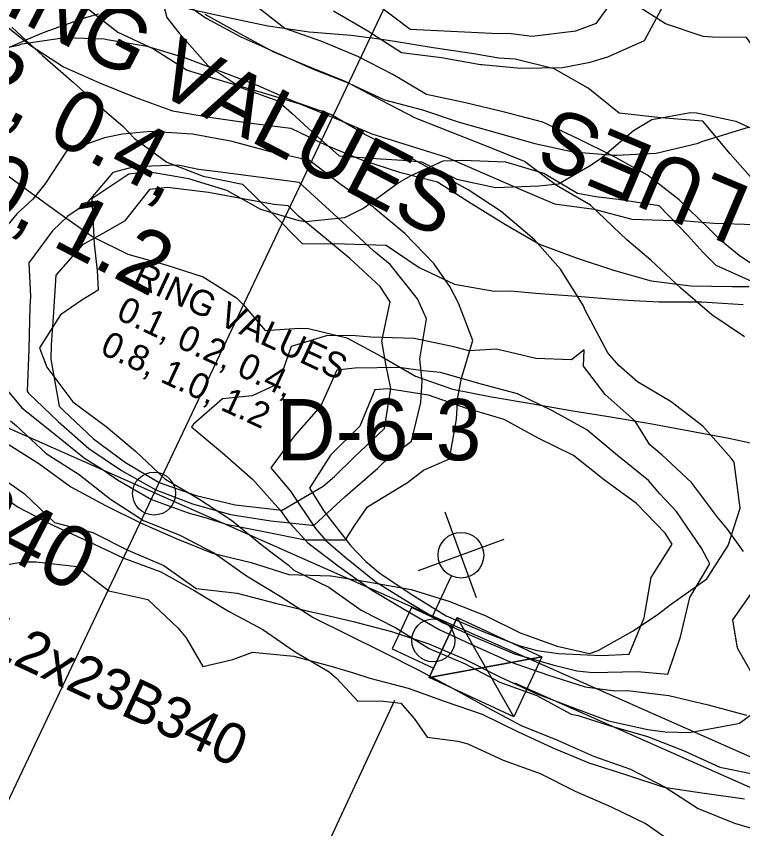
# Model space of a CAD drawing. Extents: x 1638506 to 1658005, y 834807 to 846788.
# Drawn here: x 1639685 to 1639827.3, y 842760 to 842919.2 of the extents above; entities that cross this region are included whole.
import ezdxf

# ---------------------------------------------------------------- set-up
doc = ezdxf.new("R2010")
doc.units = 0
for name, color, linetype in [('Default', 7, 'Continuous'), ('Old_Level_1', 7, 'Continuous'), ('Old_Level_2', 7, 'Continuous'), ('Scratch_Level_0', 7, 'Continuous')]:
    doc.layers.add(name, color=color, linetype=linetype)

msp = doc.modelspace()

# ---------------------------------------------------------------- linework, layer by layer
at = {"layer": 'Default'}
for p, q in [((1639775.15, 842805.23), (1639769.04, 842822.02)), ((1639780.52, 842816.67), (1639763.7, 842810.57)), ((1639772.12, 842813.64), (1639772.12, 842813.64)), ((1639766.45, 842801.47), (1639770.23, 842809.58)), ((1639773.64, 842809.38), (1639773.64, 842809.38)), ((1639782.45, 842781.94), (1639771.36, 842801.42)), ((1639787.93, 842793.69), (1639765.88, 842789.67)), ((1639782.61, 842788.6), (1640040.31, 842674.21)), ((1639689.98, 842636.62), (1639759.17, 842785.21))]:
    msp.add_line(p, q, dxfattribs=at)
for points in [[(1639766.73, 842791.5), (1639770.5, 842799.58), (1639762.39, 842803.36), (1639758.62, 842795.28)], [(1639782.45, 842781.94), (1639765.88, 842789.67), (1639771.36, 842801.42), (1639787.93, 842793.69)], [(1639776.9, 842791.68), (1639771.36, 842801.42), (1639765.88, 842789.67)], [(1639776.9, 842791.68), (1639787.93, 842793.69), (1639782.45, 842781.94)]]:
    msp.add_lwpolyline(points, close=True, dxfattribs=at)
msp.add_circle((1639772.1, 842813.61), 4.47, dxfattribs=at)
at = {"layer": 'Old_Level_1'}
for points in [[(1639755.76, 842921.47), (1639762.13, 842916.6), (1639770.13, 842916.23), (1639778.14, 842915.86), (1639781.95, 842915.75), (1639786.07, 842915.28), (1639794.59, 842916.33), (1639798.63, 842917.82), (1639803.27, 842924.27)], [(1639715.75, 842923.38), (1639722.21, 842918.76), (1639729.03, 842915.14), (1639736.03, 842912.01), (1639743.02, 842908.85), (1639750.16, 842906.08), (1639757.1, 842902.78), (1639764.54, 842900.85), (1639771.78, 842898.38), (1639779.17, 842896.31), (1639786.54, 842894.21), (1639794.1, 842892.6), (1639802.01, 842891.98), (1639802.61, 842891.95), (1639810.29, 842892.36), (1639818.57, 842894.28), (1639819.25, 842894.62), (1639828.42, 842897.43)], [(1639698.61, 842921.03), (1639704.93, 842916.03), (1639711.89, 842912.78), (1639718.52, 842908.61), (1639725.83, 842906.35), (1639733.2, 842904.22), (1639740.54, 842902.02), (1639747.62, 842899.1), (1639754.67, 842896.11), (1639761.99, 842893.87), (1639769.29, 842891.55), (1639776.33, 842888.52), (1639783.34, 842885.42), (1639790.4, 842882.45), (1639798.15, 842881.38), (1639805.57, 842879.4), (1639813.63, 842879.17), (1639815.45, 842879.13), (1639821.58, 842878.64), (1639829.62, 842878.35)], [(1639833.02, 842867.94), (1639826.6, 842872.28), (1639823, 842875.22), (1639820.63, 842877.58), (1639814.8, 842883.18), (1639808.61, 842888.01), (1639801.91, 842891.73), (1639795.07, 842895.17), (1639788.14, 842898.4), (1639780.62, 842900.38), (1639773.01, 842902.17), (1639765.35, 842903.85), (1639758.74, 842907.77), (1639751.93, 842911.27), (1639744.87, 842914.24), (1639737.62, 842916.78), (1639731.41, 842921.57)], [(1639747.15, 842920.19), (1639753.88, 842916.31), (1639760.48, 842912.08), (1639768.26, 842911.07), (1639775.91, 842909.73), (1639776.25, 842909.68), (1639783.78, 842908.98), (1639791.98, 842909.14), (1639797.38, 842910.13), (1639800.87, 842911.21), (1639808.02, 842914.4), (1639811.68, 842921.21)], [(1639827.63, 842856.39), (1639821.19, 842860.68), (1639815.18, 842865.89), (1639809.29, 842871.37), (1639804.61, 842875.36), (1639803.3, 842876.62), (1639797.44, 842882.15), (1639790.79, 842885.99), (1639784.56, 842890.72), (1639777.46, 842893.61), (1639770.31, 842896.38), (1639763.19, 842899.21), (1639756.39, 842902.73), (1639749.63, 842906.32), (1639742.53, 842909.2), (1639735.46, 842912.14), (1639728.71, 842915.78), (1639722, 842919.48)], [(1639681.43, 842918.55), (1639687.73, 842913.49), (1639694.31, 842909.22), (1639701.32, 842906.1), (1639708.43, 842903.26), (1639715.62, 842900.65), (1639723.28, 842899.34), (1639731.01, 842898.21), (1639738.79, 842897.21), (1639745.72, 842893.88), (1639752.8, 842890.99), (1639760.09, 842888.65), (1639767.54, 842886.74), (1639774.14, 842882.51), (1639780.79, 842878.4), (1639787.5, 842874.49), (1639794.69, 842871.87), (1639801.96, 842869.46), (1639809.33, 842867.36), (1639817.12, 842866.39), (1639825.2, 842866.23), (1639828.55, 842866.22)], [(1639825.57, 842831.82), (1639824.98, 842832.61), (1639819.46, 842838.86), (1639813.26, 842843.66), (1639806.64, 842847.57), (1639803.03, 842850.77), (1639800.84, 842853.25), (1639796.35, 842861.71), (1639796.11, 842862.44), (1639791.61, 842869.65), (1639786.47, 842875.37), (1639786.02, 842875.77), (1639779.99, 842880.93), (1639773.51, 842885.13), (1639766.81, 842888.86), (1639760.12, 842892.62), (1639753.25, 842896), (1639746.63, 842899.9), (1639739.39, 842902.47), (1639732.39, 842905.55), (1639725.21, 842908.26), (1639718.04, 842911), (1639710.66, 842913.26), (1639702.82, 842914.56), (1639702.23, 842914.65), (1639694.54, 842914.91), (1639686.13, 842913.72), (1639685.42, 842913.44), (1639676.05, 842911.44)], [(1639771.25, 842840.26), (1639771.47, 842844.57), (1639772.19, 842848.27), (1639774.42, 842855.67), (1639771.62, 842862.99), (1639769.91, 842866.21), (1639766.79, 842870.74), (1639761.11, 842876.64), (1639755.29, 842881.47), (1639755.02, 842881.68), (1639748.65, 842886.14), (1639742.44, 842890.92), (1639734.79, 842892.6), (1639727.28, 842894.61), (1639726.95, 842894.69), (1639719.51, 842896.04), (1639711.33, 842896.6), (1639705.86, 842896.08), (1639702.29, 842895.32), (1639694.89, 842892.75), (1639690.65, 842886.29), (1639688.27, 842883.36), (1639685.12, 842880.43), (1639680.06, 842874.35)], [(1639764.25, 842843.53), (1639764.49, 842847.69), (1639764.08, 842852.05), (1639765.36, 842859.89), (1639763.56, 842863.8), (1639758.27, 842870.57), (1639755.03, 842873.15), (1639752.26, 842875.76), (1639746.33, 842881.16), (1639740.41, 842886.57), (1639732.47, 842887.63), (1639724.52, 842888.7), (1639720.74, 842889.14), (1639716.68, 842889.96), (1639708.09, 842889.66), (1639703.94, 842888.53), (1639698.76, 842882.51), (1639695.16, 842880.02), (1639692.12, 842877.16), (1639687.49, 842870.88), (1639687.81, 842864.27), (1639687.69, 842862.35), (1639687.52, 842853.99), (1639687.15, 842845.72), (1639687.44, 842845.37), (1639693.27, 842839.77), (1639699.26, 842834.51), (1639705.67, 842830.17), (1639712.35, 842826.39), (1639719.54, 842823.7), (1639726.99, 842821.57), (1639734.87, 842820.37), (1639742.91, 842819.51), (1639743.36, 842819.51), (1639749.46, 842825.11), (1639755.75, 842830.61), (1639757.15, 842831.94), (1639762.42, 842835.94), (1639764.25, 842843.53)], [(1639758.36, 842846.28), (1639757.46, 842850.72), (1639756.64, 842855.52), (1639758.21, 842863.23), (1639756.26, 842866.25), (1639750.37, 842871.71), (1639744.28, 842876.75), (1639740.27, 842880.03), (1639738.29, 842882.01), (1639735.5, 842882.26), (1639730.41, 842883.22), (1639722.64, 842884.65), (1639714.66, 842885.65), (1639711.1, 842885.2), (1639706.2, 842879.04), (1639702, 842876.59), (1639698.01, 842874.42), (1639692.75, 842868.43), (1639692.29, 842860.21), (1639691.88, 842854.9), (1639691.83, 842851.98), (1639693.44, 842842.78), (1639694.29, 842841.96), (1639700.14, 842836.4), (1639706.42, 842831.77), (1639713.02, 842827.83), (1639720.28, 842825.3), (1639727.87, 842823.47), (1639735.89, 842822.56), (1639737.07, 842822.44), (1639745.15, 842827.11), (1639747.35, 842829.03), (1639751.15, 842832.75), (1639757.16, 842838.39), (1639758.36, 842846.28)], [(1639680.99, 842848.59), (1639686.1, 842842.5), (1639692.25, 842837.58), (1639698.37, 842832.61), (1639701.83, 842830.43), (1639704.84, 842828.37), (1639711.48, 842824.53), (1639718.7, 842821.91), (1639722.21, 842820.93), (1639726.1, 842819.68), (1639733.85, 842818.18), (1639741.57, 842816.63), (1639749.52, 842816.64), (1639751.34, 842819.48), (1639753.83, 842823.06), (1639761.63, 842827.87), (1639764.79, 842830.23), (1639769.84, 842832.48), (1639771.25, 842840.26)], [(1639682.93, 842835.69), (1639689.44, 842831.55), (1639695.74, 842826.98), (1639702.5, 842823.37), (1639709.37, 842819.98), (1639716.37, 842816.9), (1639723.48, 842814.04), (1639731.04, 842812.15), (1639738.39, 842809.82), (1639746.57, 842809.57), (1639746.71, 842809.55), (1639754.56, 842808.29), (1639762.36, 842806.91), (1639769.73, 842804.63), (1639776.85, 842801.79), (1639783.72, 842798.43), (1639790.92, 842795.77), (1639797.24, 842794.38), (1639798.99, 842794.97), (1639805.81, 842798.83), (1639810.76, 842802.1), (1639813.09, 842803.87), (1639820.21, 842808.99), (1639824.41, 842815.48), (1639826.8, 842822.8), (1639825.57, 842831.82)], [(1639680.3, 842830.06), (1639686.66, 842825.6), (1639692.51, 842820.04), (1639700.04, 842818.08), (1639706.85, 842814.58), (1639713.9, 842811.61), (1639720.24, 842807.11), (1639728.26, 842806.2), (1639735.77, 842804.2), (1639743.35, 842802.36), (1639744.1, 842802.28), (1639750.98, 842800.63), (1639758.52, 842798.68), (1639765.82, 842796.24), (1639772.88, 842793.28), (1639779.69, 842789.78), (1639786.63, 842786.56), (1639793.8, 842783.83), (1639801, 842781.18), (1639808.66, 842779.5), (1639812.1, 842779.01), (1639816.83, 842778.92), (1639826.03, 842780.56), (1639826.61, 842780.69), (1639833.65, 842785.85)], [(1639679.95, 842811.21), (1639686.35, 842812.33), (1639688.9, 842812.31), (1639696.93, 842811.42), (1639703.15, 842806.66), (1639710.8, 842804.96), (1639716.64, 842799.38), (1639718.29, 842797.43), (1639721.55, 842791.81), (1639727.44, 842793.17), (1639731.31, 842794.64), (1639739.37, 842793.82), (1639746.89, 842791.84), (1639751.25, 842790.5), (1639754.25, 842789.54), (1639761.78, 842787.58), (1639768.99, 842784.94), (1639776.28, 842782.46), (1639783.15, 842779.09), (1639790.1, 842775.9), (1639797.17, 842772.97), (1639804.5, 842770.57), (1639811.84, 842768.21), (1639819.71, 842767), (1639819.77, 842766.99), (1639827.63, 842765.88)]]:
    msp.add_lwpolyline(points, dxfattribs=at)
msp.add_circle((1639712.02, 842825.68), 4.21, dxfattribs=at)
at = {"layer": 'Old_Level_2'}
for p, q in [((1639805.78, 843023.38), (1639662.97, 842722.48)), ((1639680.46, 842839.86), (1639907.01, 842739.41))]:
    msp.add_line(p, q, dxfattribs=at)
at = {"layer": 'Scratch_Level_0'}
for points in [[(1639712.78, 842925.67), (1639714.52, 842918.88), (1639716.92, 842915.84), (1639722.53, 842909.48), (1639729.02, 842905.18), (1639736.22, 842902.57), (1639739.01, 842900.18), (1639742.24, 842897.17), (1639748.27, 842891.8), (1639756.33, 842891.2), (1639760.73, 842890.97), (1639764.39, 842890.62), (1639771.27, 842887.26), (1639778.88, 842885.59), (1639787.35, 842885.97), (1639791.2, 842886.36), (1639797.29, 842889.83), (1639799.34, 842891.22), (1639805.88, 842896.75), (1639809.46, 842898.93), (1639817.04, 842900.33), (1639818.31, 842900.21), (1639825.94, 842898.61), (1639832.9, 842895.42)], [(1639908.21, 842853.63), (1639902.07, 842858.41), (1639896.06, 842863.44), (1639890.06, 842868.47), (1639884.12, 842873.64), (1639883.49, 842874.18), (1639878.21, 842878.87), (1639872.24, 842883.96), (1639866.28, 842889.09), (1639860.23, 842894.04), (1639853.68, 842898.01), (1639846.42, 842900.65), (1639839.32, 842903.56), (1639833.09, 842908.17), (1639831.92, 842909.58), (1639828, 842914.97), (1639821.34, 842915.08), (1639819.51, 842915.22), (1639812.16, 842917.67), (1639805.69, 842921.8)], [(1639701.09, 842919.58), (1639698.12, 842918.74), (1639690.64, 842916.06), (1639688.44, 842915.15), (1639679.52, 842911.24)], [(1639830.23, 842886.06), (1639824.82, 842892.24), (1639819.49, 842898.58), (1639811.24, 842899.29), (1639803.07, 842900.16), (1639797, 842905.06), (1639790.34, 842908.84), (1639782.72, 842910.77), (1639779.49, 842910.96), (1639774.64, 842911.81), (1639766.64, 842913), (1639758.69, 842914.3), (1639755.64, 842914.72), (1639750.63, 842915.38), (1639742.36, 842916.04), (1639734.33, 842917.18), (1639734.3, 842917.19), (1639726.57, 842918.85), (1639718.83, 842920.55)], [(1639684.17, 842917.01), (1639687.87, 842913.56), (1639690.14, 842911.48), (1639696.21, 842906.19), (1639702.22, 842900.77), (1639705.97, 842897.58), (1639708.17, 842895.21), (1639714.51, 842890.57), (1639721.66, 842887.84), (1639729.31, 842886.28), (1639735.19, 842880.54), (1639740.99, 842874.63), (1639749.27, 842874.56), (1639757.48, 842874.33), (1639763.92, 842869.92), (1639770.85, 842866.67), (1639778.6, 842865.34), (1639781.83, 842865.4), (1639786.73, 842864.93), (1639794.8, 842864.37), (1639802.83, 842863.69), (1639805.9, 842863.51), (1639810.94, 842863.24), (1639819.25, 842863.23), (1639827.34, 842862.71)], [(1639829.05, 842867.19), (1639822.07, 842870.35), (1639819.47, 842872.95), (1639816.49, 842876.2), (1639810.89, 842882.03), (1639802.91, 842883.25), (1639798.53, 842883.82), (1639794.91, 842884.46), (1639788.31, 842888.34), (1639780.86, 842890.6), (1639772.39, 842890.88), (1639768.52, 842890.79), (1639762.17, 842887.81), (1639760.03, 842886.58), (1639753.07, 842881.57), (1639749.33, 842879.68), (1639741.67, 842878.88), (1639740.41, 842879.1), (1639732.93, 842881.29), (1639726.24, 842885.01), (1639718.82, 842887.33), (1639710.89, 842888.66), (1639707.08, 842888.22), (1639699.82, 842883.37), (1639700.31, 842874.5), (1639700.88, 842869.39), (1639701.07, 842865.48), (1639697.84, 842863.53), (1639693.69, 842860.7), (1639689.6, 842854.2), (1639691.04, 842850.44), (1639696.12, 842843.63), (1639702.36, 842839.03), (1639702.64, 842838.81), (1639708.35, 842833.98), (1639714.15, 842828.54), (1639720.75, 842824.66), (1639727.18, 842820.44), (1639733.24, 842815.51), (1639738.32, 842811.65), (1639739.37, 842810.71), (1639746.23, 842807.32), (1639752.53, 842802.85), (1639759.34, 842799.37), (1639765.88, 842795.36), (1639772.92, 842792.32), (1639779.68, 842788.75), (1639786.96, 842786.16), (1639793.68, 842782.5), (1639795.05, 842782.19), (1639801.13, 842780.25), (1639808.65, 842778.13), (1639815.8, 842775.3), (1639822.77, 842772.12), (1639830.55, 842770.51)], [(1639680.91, 842889.71), (1639687.26, 842885.1), (1639693.6, 842880.45), (1639700.01, 842875.98), (1639706.86, 842872.53), (1639714.3, 842870.47), (1639721.61, 842868.12), (1639728.17, 842864.01), (1639729.45, 842862.69), (1639733.78, 842857.62), (1639740.43, 842858.04), (1639742.26, 842858.03), (1639749.78, 842856.17), (1639756.55, 842852.55), (1639763.2, 842848.64), (1639770.44, 842846.11), (1639778.11, 842844.61), (1639785.86, 842843.29), (1639793.59, 842841.92), (1639800.57, 842840.84), (1639801.38, 842840.7), (1639809.15, 842839.41), (1639816.85, 842837.98), (1639824.56, 842836.56), (1639832.15, 842834.87)], [(1639827.44, 842814.31), (1639824.26, 842818.74), (1639822.33, 842821.07), (1639817.22, 842827.83), (1639811.41, 842833.24), (1639809.07, 842835.25), (1639806.24, 842839.88), (1639800.31, 842845.06), (1639796.08, 842850.62), (1639796.25, 842853.83), (1639793.72, 842851.84), (1639786.73, 842852.11), (1639779.08, 842853.98), (1639773.67, 842853.64), (1639770.68, 842854.4), (1639762.91, 842856.04), (1639754.44, 842856.33), (1639751.43, 842856.57), (1639745.98, 842856.63), (1639738.88, 842854.47), (1639736.28, 842847.2), (1639731.21, 842844.8), (1639725.42, 842844.21), (1639719.73, 842839.29), (1639719.35, 842838.75), (1639719.41, 842838.68), (1639725.43, 842833.67), (1639731.35, 842828.46), (1639736.8, 842822.37), (1639738.19, 842820.34), (1639742.13, 842816.02), (1639748.32, 842811.35), (1639754.59, 842806.82), (1639761.19, 842802.94), (1639767.81, 842799.09), (1639774.77, 842795.89), (1639781.74, 842792.71), (1639789.05, 842790.2), (1639796.44, 842787.81), (1639802.23, 842787.08), (1639804.69, 842787.11), (1639812.81, 842786.15), (1639820.48, 842784.3), (1639828.03, 842782.26)], [(1639820.84, 842811.89), (1639819.18, 842815), (1639814.29, 842822.18), (1639811.04, 842825.6), (1639808.81, 842828.23), (1639802.75, 842833.15), (1639796.74, 842838.18), (1639790.04, 842841.88), (1639783.16, 842845.24), (1639775.59, 842847.25), (1639768.08, 842849.39), (1639764.65, 842849.7), (1639759.98, 842850.39), (1639751.29, 842850.26), (1639747.79, 842849.84), (1639744.64, 842842.85), (1639739.46, 842836.92), (1639734.87, 842830.69), (1639738.75, 842826.12), (1639743.59, 842818.83), (1639745.63, 842816.48), (1639749.34, 842813.31), (1639755.42, 842808.42), (1639761.93, 842804.35), (1639768.5, 842800.42), (1639775.5, 842797.3), (1639782.57, 842794.32), (1639790.07, 842792.15), (1639794.8, 842790.94), (1639797.9, 842790.62), (1639806.64, 842790.85), (1639812.61, 842790.31), (1639815.07, 842797.65), (1639816.94, 842805.3), (1639820.84, 842811.89)], [(1639813.43, 842815.74), (1639812.09, 842817.95), (1639806.49, 842823.76), (1639800.21, 842828.28), (1639794.12, 842833.15), (1639787.25, 842836.5), (1639780.55, 842840.2), (1639773.06, 842842.38), (1639765.76, 842844.92), (1639757.78, 842846.16), (1639755.21, 842845.98), (1639752.27, 842838.89), (1639746.57, 842833.23), (1639742.44, 842826.76), (1639745.32, 842822.18), (1639750.47, 842815.48), (1639753.39, 842812.45), (1639756.25, 842810.03), (1639762.66, 842805.76), (1639769.2, 842801.75), (1639776.24, 842798.71), (1639783.41, 842795.92), (1639787.03, 842794.97), (1639791.2, 842794.33), (1639799.63, 842793.97), (1639805.04, 842794.24), (1639807.96, 842801.34), (1639809.31, 842809.26), (1639813.43, 842815.74)], [(1639683.93, 842839.91), (1639685.05, 842838.92), (1639690.89, 842833.54), (1639697.36, 842829.42), (1639703.48, 842824.6), (1639709.93, 842820.42), (1639717.06, 842817.56), (1639723.86, 842814.04), (1639730.14, 842809.54), (1639736.71, 842805.59), (1639743.16, 842801.41), (1639750, 842797.99), (1639756.88, 842794.64), (1639763.7, 842791.17), (1639770.46, 842787.59), (1639777.16, 842783.88), (1639783.89, 842780.26), (1639791.02, 842777.38), (1639798.03, 842774.28), (1639805.32, 842771.73), (1639812.11, 842768.19), (1639818.55, 842764), (1639825.68, 842761.13), (1639833.14, 842758.9)], [(1639679.07, 842827.4), (1639685.42, 842823.02), (1639692.2, 842819.49), (1639699.18, 842816.32), (1639706.08, 842813.01), (1639713.33, 842810.37), (1639720.02, 842806.66), (1639726.56, 842802.64), (1639733.31, 842799.04), (1639739.65, 842794.66), (1639746.27, 842790.8), (1639747.76, 842789.51), (1639751.9, 842785.04), (1639756.32, 842785.07), (1639760.31, 842784.65), (1639762.95, 842781.62), (1639765.47, 842777.99), (1639771.5, 842777.18), (1639773.42, 842776.69), (1639780.39, 842773.5), (1639787.62, 842770.83), (1639794.44, 842767.38), (1639801.49, 842764.34), (1639808.37, 842761), (1639814.7, 842756.59)], [(1639829.11, 842790.36), (1639826.26, 842795.43), (1639825.3, 842800.95), (1639829.75, 842807.26)]]:
    msp.add_lwpolyline(points, dxfattribs=at)
msp.add_circle((1639766.69, 842796.92), 4.21, dxfattribs=at)

# ---------------------------------------------------------------- texts
at = {"layer": 'Default'}
msp.add_text('D-6-3', height=12, dxfattribs=at).set_placement((1639735.96, 842832.2))
at = {"layer": 'Old_Level_1'}
for s, height, p in [('RING VALUES', 5, (1639707.55, 842866.78)), ('0.1, 0.2, 0.4,', 5, (1639704.38, 842859.98)), ('0.8, 1.0, 1.2', 5, (1639701.21, 842853.18)), ('GE ERL2x23B340', 8, (1639648.57, 842808.9))]:
    msp.add_text(s, height=height, rotation=335, dxfattribs=at).set_placement(p)
at = {"layer": 'Scratch_Level_0'}
for s, rotation, p in [('RING VALUES', 332.5519, (1639671.94, 842925.24)), ('0.1, 0.2, 0.4,', 332.5519, (1639635.26, 842924)), ('0.8, 1.0, 1.2', 332.5519, (1639636.35, 842903.15)), ('RING VALUES', 157.0176, (1639890.17, 842859.54)), ('GE ERL2x23C340', 332.5519, (1639579.27, 842866.97))]:
    msp.add_text(s, height=12, rotation=rotation, dxfattribs=at).set_placement(p)

doc.saveas('drawing.dxf')
